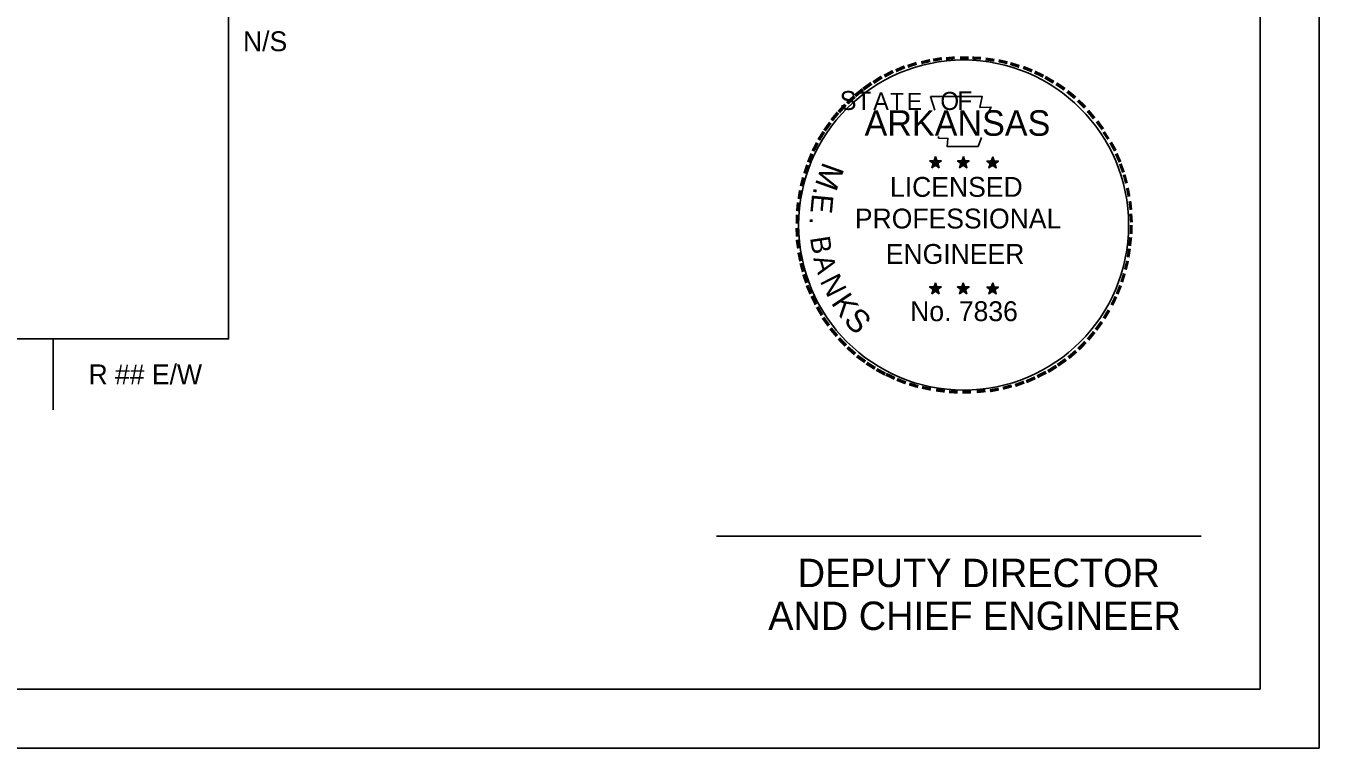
# Model space of a CAD drawing. Extents: x -0.25 to 1.42, y 0 to 0.92.
# Drawn here: x 0.9604 to 1.4167, y 0 to 0.2547 of the extents above; entities that cross this region are included whole.
import ezdxf

# ---------------------------------------------------------------- set-up
doc = ezdxf.new("R2010")
doc.units = 0
for name, color, linetype in [('DSN_DRFT_DNC', 7, 'Continuous'), ('SHET_Annotations', 7, 'Continuous'), ('SHET_Border-Lines', 7, 'Continuous')]:
    doc.layers.add(name, color=color, linetype=linetype)

msp = doc.modelspace()

# ---------------------------------------------------------------- linework, layer by layer
at = {"layer": 'DSN_DRFT_DNC'}
msp.add_lwpolyline([(0.38477, 0.54167), (1.0319, 0.54167), (1.0319, 0.1443), (0.38477, 0.1443)], close=True, dxfattribs=at)
at = {"layer": 'SHET_Annotations'}
for p, q in [((1.27928, 0.20707), (1.28133, 0.20641)), ((1.27928, 0.20707), (1.28079, 0.20683)), ((1.27928, 0.20707), (1.28067, 0.20635)), ((1.28007, 0.20466), (1.28133, 0.20641)), ((1.28007, 0.20466), (1.28079, 0.20611)), ((1.28007, 0.20466), (1.28127, 0.20593)), ((1.28133, 0.20858), (1.28109, 0.20707)), ((1.2826, 0.20466), (1.28127, 0.20593)), ((1.28133, 0.20641), (1.28133, 0.20858)), ((1.28133, 0.20858), (1.28164, 0.20713)), ((1.28333, 0.20707), (1.28133, 0.20641)), ((1.2826, 0.20466), (1.28133, 0.20641)), ((1.28333, 0.20707), (1.2817, 0.20677)), ((1.2826, 0.20466), (1.28176, 0.20635)), ((1.28333, 0.20707), (1.28218, 0.20647)), ((1.28912, 0.20707), (1.29117, 0.20641)), ((1.28912, 0.20707), (1.29057, 0.20683)), ((1.28912, 0.20707), (1.29045, 0.20635)), ((1.28984, 0.20466), (1.29117, 0.20641)), ((1.28984, 0.20466), (1.29063, 0.20611)), ((1.28984, 0.20466), (1.29111, 0.20593)), ((1.29117, 0.20858), (1.29093, 0.20707)), ((1.29238, 0.20466), (1.29111, 0.20593)), ((1.29117, 0.20641), (1.29117, 0.20858)), ((1.29117, 0.20858), (1.29141, 0.20713)), ((1.29316, 0.20707), (1.29117, 0.20641)), ((1.29238, 0.20466), (1.29117, 0.20641)), ((1.29316, 0.20707), (1.29147, 0.20677)), ((1.29238, 0.20466), (1.29153, 0.20635)), ((1.29316, 0.20707), (1.29196, 0.20647)), ((1.29944, 0.20701), (1.30149, 0.20635)), ((1.29944, 0.20701), (1.30089, 0.20671)), ((1.29944, 0.20701), (1.30083, 0.20629)), ((1.30016, 0.2046), (1.30149, 0.20635)), ((1.30016, 0.2046), (1.30095, 0.20605)), ((1.30016, 0.2046), (1.30149, 0.20587)), ((1.30149, 0.20846), (1.30125, 0.20701)), ((1.30149, 0.20635), (1.30149, 0.20846)), ((1.30149, 0.20846), (1.30173, 0.20701)), ((1.30354, 0.20701), (1.30149, 0.20635)), ((1.3027, 0.2046), (1.30149, 0.20635)), ((1.3027, 0.2046), (1.30149, 0.20587)), ((1.30354, 0.20701), (1.30179, 0.20671)), ((1.3027, 0.2046), (1.30191, 0.20629)), ((1.30354, 0.20701), (1.30228, 0.20641)), ((1.27922, 0.16266), (1.28127, 0.16199)), ((1.27922, 0.16266), (1.28079, 0.16235)), ((1.27922, 0.16266), (1.28067, 0.16193)), ((1.28007, 0.16024), (1.28127, 0.16199)), ((1.28007, 0.16024), (1.28079, 0.16169)), ((1.28007, 0.16024), (1.28127, 0.16157)), ((1.28127, 0.1641), (1.28103, 0.16266)), ((1.28127, 0.16199), (1.28127, 0.1641)), ((1.28127, 0.1641), (1.28158, 0.16266)), ((1.28333, 0.16266), (1.28127, 0.16199)), ((1.2826, 0.16024), (1.28127, 0.16199)), ((1.2826, 0.16024), (1.28127, 0.16151)), ((1.28333, 0.16266), (1.28164, 0.16235)), ((1.2826, 0.16024), (1.28176, 0.16193)), ((1.28333, 0.16266), (1.28218, 0.16205)), ((1.28906, 0.16266), (1.29111, 0.16199)), ((1.28906, 0.16266), (1.29057, 0.16235)), ((1.28906, 0.16266), (1.29045, 0.16193)), ((1.28984, 0.16024), (1.29111, 0.16199)), ((1.28984, 0.16024), (1.29057, 0.16169)), ((1.28984, 0.16024), (1.29111, 0.16157)), ((1.29111, 0.1641), (1.29087, 0.16266)), ((1.29111, 0.16199), (1.29111, 0.1641)), ((1.29111, 0.1641), (1.29135, 0.16266)), ((1.29316, 0.16266), (1.29111, 0.16199)), ((1.29232, 0.16024), (1.29111, 0.16199)), ((1.29232, 0.16024), (1.29111, 0.16151)), ((1.29316, 0.16266), (1.29141, 0.16235)), ((1.29232, 0.16024), (1.29153, 0.16193)), ((1.29316, 0.16266), (1.2919, 0.16205)), ((1.29944, 0.1626), (1.30149, 0.16193)), ((1.29944, 0.1626), (1.30089, 0.16229)), ((1.29944, 0.1626), (1.30083, 0.16187)), ((1.30016, 0.16018), (1.30149, 0.16193)), ((1.30016, 0.16018), (1.30095, 0.16163)), ((1.30016, 0.16018), (1.30149, 0.16151)), ((1.30149, 0.16404), (1.30125, 0.1626)), ((1.30149, 0.16193), (1.30149, 0.16404)), ((1.30149, 0.16404), (1.30173, 0.1626)), ((1.30354, 0.1626), (1.30149, 0.16193)), ((1.3027, 0.16018), (1.30149, 0.16193)), ((1.3027, 0.16018), (1.30149, 0.16145)), ((1.30354, 0.1626), (1.30179, 0.16229)), ((1.3027, 0.16018), (1.30185, 0.16187)), ((1.30354, 0.1626), (1.30228, 0.16199)), ((0.97, 0.1443), (0.97, 0.1193)), ((1.20407, 0.07469), (1.375, 0.07469))]:
    msp.add_line(p, q, dxfattribs=at)
for points in [[(1.27952, 0.22982), (1.28109, 0.22494)], [(1.3001, 0.22445), (1.30095, 0.22608), (1.29696, 0.22596), (1.29775, 0.22982), (1.27952, 0.22982)], [(1.28242, 0.21564), (1.28242, 0.2151), (1.28568, 0.21498), (1.28538, 0.2122), (1.29636, 0.2122), (1.29757, 0.21534)], [(1.28133, 0.20858), (1.2826, 0.20466), (1.27928, 0.20707), (1.28333, 0.20707), (1.28007, 0.20466), (1.28133, 0.20858)], [(1.29117, 0.20858), (1.29238, 0.20466), (1.28912, 0.20707), (1.29316, 0.20707), (1.28984, 0.20466), (1.29117, 0.20858)], [(1.30149, 0.20846), (1.3027, 0.2046), (1.29944, 0.20701), (1.30354, 0.20701), (1.30016, 0.2046), (1.30149, 0.20846)], [(1.28127, 0.1641), (1.2826, 0.16024), (1.27922, 0.16266), (1.28333, 0.16266), (1.28007, 0.16024), (1.28127, 0.1641)], [(1.29111, 0.1641), (1.29232, 0.16024), (1.28906, 0.16266), (1.29316, 0.16266), (1.28984, 0.16024), (1.29111, 0.1641)], [(1.30149, 0.16404), (1.3027, 0.16018), (1.29944, 0.1626), (1.30354, 0.1626), (1.30016, 0.16018), (1.30149, 0.16404)]]:
    msp.add_lwpolyline(points, dxfattribs=at)
for centre, radius in [((1.29125, 0.18445), 0.05821), ((1.28128, 0.2064), 0.00101), ((1.28128, 0.2064), 0.000848), ((1.28128, 0.2064), 0.000679), ((1.28128, 0.2064), 0.000581), ((1.28128, 0.2064), 0.000438), ((1.28128, 0.2064), 0.000291), ((1.28128, 0.2064), 0.000174), ((1.29108, 0.2064), 0.00101), ((1.29108, 0.2064), 0.000848), ((1.29108, 0.2064), 0.000679), ((1.29108, 0.2064), 0.000581), ((1.29108, 0.2064), 0.000438), ((1.29108, 0.2064), 0.000291), ((1.29108, 0.2064), 0.000174), ((1.30142, 0.20633), 0.00101), ((1.30142, 0.20633), 0.000848), ((1.30142, 0.20633), 0.000679), ((1.30142, 0.20633), 0.000581), ((1.30142, 0.20633), 0.000438), ((1.30142, 0.20633), 0.000291), ((1.30142, 0.20633), 0.000174), ((1.28126, 0.16198), 0.00101), ((1.28126, 0.16198), 0.000848), ((1.28126, 0.16198), 0.000679), ((1.28126, 0.16198), 0.000581), ((1.28126, 0.16198), 0.000438), ((1.28126, 0.16198), 0.000291), ((1.28126, 0.16198), 0.000174), ((1.29105, 0.16198), 0.00101), ((1.29105, 0.16198), 0.000848), ((1.29105, 0.16198), 0.000679), ((1.29105, 0.16198), 0.000581), ((1.29105, 0.16198), 0.000438), ((1.29105, 0.16198), 0.000291), ((1.29105, 0.16198), 0.000174), ((1.30141, 0.16192), 0.00101), ((1.30141, 0.16192), 0.000848), ((1.30141, 0.16192), 0.000679), ((1.30141, 0.16192), 0.000581), ((1.30141, 0.16192), 0.000438), ((1.30141, 0.16192), 0.000291), ((1.30141, 0.16192), 0.000174)]:
    msp.add_circle(centre, radius, dxfattribs=at)
at = {"layer": 'SHET_Border-Lines'}
for points in [[(0, 0), (1.41667, 0), (1.41667, 0.91667), (0, 0.91667)], [(0.02083, 0.02083), (1.39583, 0.02083), (1.39583, 0.89583), (0.02083, 0.89583)]]:
    msp.add_lwpolyline(points, close=True, dxfattribs=at)

# ---------------------------------------------------------------- texts
at = {"layer": 'SHET_Annotations'}
for s, height, p in [('N/S', 0.007, (1.037, 0.24576)), ('S', 0.00667, (1.24751, 0.22504)), ('T', 0.00641, (1.25343, 0.22504)), ('A', 0.00617, (1.25935, 0.22504)), ('T', 0.00602, (1.26527, 0.22504)), ('E', 0.00602, (1.27119, 0.22504)), ('O', 0.00637, (1.28303, 0.22504)), ('F', 0.0066, (1.28895, 0.22504)), ('ARKANSAS', 0.009, (1.25629, 0.21593)), ('LICENSED', 0.007, (1.26526, 0.19441)), ('PROFESSIONAL', 0.007, (1.25287, 0.18325)), ('ENGINEER', 0.007, (1.26378, 0.17076)), ('No. 7836', 0.007, (1.27238, 0.15057)), ('R ## E/W', 0.007, (0.9825, 0.1283)), ('DEPUTY DIRECTOR', 0.01, (1.23271, 0.0568)), ('AND CHIEF ENGINEER', 0.01, (1.2223, 0.04167))]:
    msp.add_text(s, height=height, dxfattribs=at).set_placement(p)
for s, height, rotation, p in [('-', 0.01024, 19.1761, (1.27222, 0.23646)), ('-', 0.00989, 13.6301, (1.27663, 0.23785)), ('-', 0.00969, 10.2193, (1.28055, 0.23882)), ('-', 0.00949, 5.8968, (1.28484, 0.23942)), ('-', 0.00939, 0.1862, (1.28936, 0.23984)), ('-', 0.0094, 357.743, (1.29359, 0.23978)), ('-', 0.00957, 352.1617, (1.29793, 0.23942)), ('-', 0.00984, 347.2049, (1.30215, 0.23882)), ('-', 0.01015, 342.3362, (1.30596, 0.23785)), ('-', 0.01075, 28.7918, (1.26474, 0.23302)), ('-', 0.01054, 24.3072, (1.26842, 0.23489)), ('-', 0.01042, 337.8551, (1.31018, 0.23658)), ('-', 0.01062, 334.1211, (1.31392, 0.23501)), ('-', 0.01095, 38.9507, (1.25508, 0.22632)), ('-', 0.01093, 36.2317, (1.2578, 0.22856)), ('-', 0.0109, 34.0636, (1.26124, 0.23085)), ('-', 0.0108, 329.6409, (1.3173, 0.23332)), ('-', 0.0109, 325.8627, (1.32104, 0.23121)), ('-', 0.01093, 42.9622, (1.25255, 0.22385)), ('-', 0.01095, 320.5297, (1.32466, 0.22874)), ('-', 0.0109, 315.5786, (1.32816, 0.22584)), ('-', 0.01075, 50.6142, (1.24748, 0.21824)), ('-', 0.01081, 48.4231, (1.24989, 0.22101)), ('-', 0.01076, 309.8797, (1.33148, 0.22258)), ('-', 0.01061, 54.2325, (1.24513, 0.21486)), ('-', 0.01065, 306.6522, (1.33462, 0.21908)), ('-', 0.01045, 58.0706, (1.2432, 0.21178)), ('-', 0.00921, 303.6753, (1.3374, 0.21576)), ('-', 0.01022, 62.8713, (1.24132, 0.20816)), ('-', 0.01034, 299.6684, (1.33933, 0.21214)), ('-', 0.01011, 294.6628, (1.34126, 0.20858)), ('-', 0.00979, 72.3945, (1.23861, 0.20092)), ('-', 0.00999, 67.7743, (1.23982, 0.2046)), ('M', 0.00802, 250.354, (1.24167, 0.20701)), ('-', 0.00992, 290.5728, (1.34271, 0.20526)), ('-', 0.00967, 75.461, (1.2374, 0.19669)), ('-', 0.00969, 285.1233, (1.3441, 0.20182)), ('-', 0.00949, 81.2013, (1.23668, 0.19253)), ('.', 0.00763, 261.0526, (1.23844, 0.19803)), ('-', 0.00954, 280.5493, (1.3453, 0.19742)), ('-', 0.00942, 85.1863, (1.23619, 0.18849)), ('E', 0.00763, 264.6298, (1.23779, 0.19567)), ('-', 0.00945, 276.5962, (1.34621, 0.19301)), ('-', 0.00939, 89.0622, (1.23607, 0.18438)), ('-', 0.00941, 274.3301, (1.34657, 0.18873)), ('-', 0.00941, 94.1959, (1.23625, 0.1801)), ('.', 0.00719, 271.7903, (1.23686, 0.18728)), ('-', 0.00939, 269.9407, (1.34675, 0.18498)), ('-', 0.0095, 98.9479, (1.23668, 0.17623)), ('B', 0.007, 278.9474, (1.23701, 0.18)), ('-', 0.00944, 263.5172, (1.34663, 0.18112)), ('-', 0.00957, 101.7149, (1.23746, 0.17189)), ('-', 0.0095, 260.9953, (1.34621, 0.17726)), ('-', 0.0097, 105.4578, (1.23843, 0.16839)), ('A', 0.00708, 286.087, (1.23814, 0.17274)), ('-', 0.00966, 255.7626, (1.34561, 0.17328)), ('-', 0.00985, 109.0874, (1.23963, 0.16471)), ('N', 0.00743, 296.7339, (1.2404, 0.16475)), ('-', 0.00977, 252.8681, (1.34452, 0.16905)), ('-', 0.01008, 114.0643, (1.24114, 0.16121)), ('K', 0.00782, 303.7708, (1.24429, 0.15704)), ('-', 0.00999, 247.8887, (1.34325, 0.16513)), ('-', 0.01016, 115.7289, (1.24295, 0.15759)), ('-', 0.01038, 120.4471, (1.24507, 0.15415)), ('-', 0.01014, 244.6197, (1.34168, 0.16145)), ('-', 0.01062, 125.8934, (1.24736, 0.15089)), ('S', 0.00808, 314.2033, (1.24853, 0.15052)), ('-', 0.01063, 233.8452, (1.33704, 0.15324)), ('-', 0.0104, 239.0712, (1.33939, 0.15704)), ('-', 0.01079, 130.7181, (1.25014, 0.14757)), ('-', 0.01072, 231.2538, (1.3345, 0.14986)), ('-', 0.01088, 134.2238, (1.25315, 0.14443)), ('-', 0.01094, 138.9338, (1.25623, 0.14172)), ('-', 0.01088, 225.7653, (1.33166, 0.1466)), ('-', 0.01092, 144.6463, (1.25949, 0.1393)), ('-', 0.01093, 215.7363, (1.32539, 0.14087)), ('-', 0.01094, 221.0851, (1.32865, 0.14359)), ('-', 0.01085, 148.0898, (1.26275, 0.13713)), ('-', 0.01073, 151.5704, (1.26613, 0.1352)), ('-', 0.0106, 154.6002, (1.26927, 0.13381)), ('-', 0.01069, 207.3568, (1.31899, 0.13653)), ('-', 0.01086, 212.2491, (1.32231, 0.13858)), ('-', 0.01038, 158.5612, (1.27289, 0.1323)), ('-', 0.01012, 162.7983, (1.27693, 0.13103)), ('-', 0.00982, 167.5555, (1.28109, 0.13013)), ('-', 0.01001, 195.4743, (1.30777, 0.13164)), ('-', 0.01034, 200.7184, (1.31175, 0.13303)), ('-', 0.01054, 204.2516, (1.31537, 0.13459)), ('-', 0.00953, 173.1155, (1.28562, 0.12946)), ('-', 0.00942, 176.5183, (1.28991, 0.12911)), ('-', 0.00939, 181.5918, (1.29431, 0.12923)), ('-', 0.00949, 185.8167, (1.29914, 0.12971)), ('-', 0.00975, 191.2858, (1.30348, 0.13043))]:
    msp.add_text(s, height=height, rotation=rotation, dxfattribs=at).set_placement(p)

doc.saveas('drawing.dxf')
